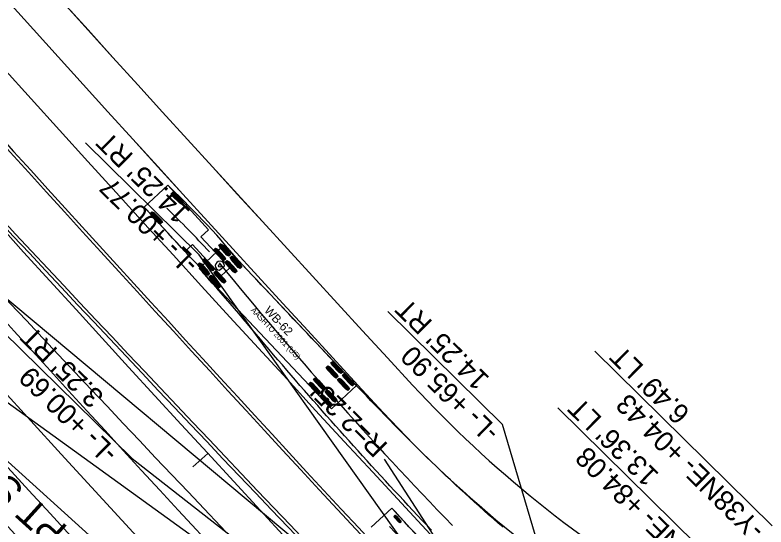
# Model space of a CAD drawing. Extents: x 1262642 to 1268358, y 767825 to 773481.
# Drawn here: x 1266608.5 to 1266795.4, y 772285.8 to 772413.2 of the extents above; entities that cross this region are included whole.
import ezdxf

# ---------------------------------------------------------------- set-up
doc = ezdxf.new("R2010")
doc.units = 0
for name, color, linetype in [('Prop Conc 1ft 6in Curb and Gutter', 7, 'Continuous'), ('Prop Dimension', 7, 'Continuous'), ('Prop Dimension Text', 7, 'Continuous'), ('Prop EOT', 7, 'Continuous'), ('Prop Horizontal Alignment', 7, 'Continuous'), ('Prop Horizontal Alignment Station Label', 7, 'Continuous'), ('Prop Horizontal Alignment Tick Small', 7, 'Continuous'), ('Prop Lane Lines', 7, 'Continuous'), ('Prop Paved Shoulder', 7, 'Continuous'), ('Prop Shade Light', 7, 'Continuous'), ('Scratch_Level_3', 7, 'Continuous')]:
    doc.layers.add(name, color=color, linetype=linetype)

msp = doc.modelspace()

# ---------------------------------------------------------------- linework, layer by layer
at = {"layer": 'Prop Conc 1ft 6in Curb and Gutter'}
for centre, radius, start, end in [((1275047.31, 780021.23), 11385.75, 220.946412, 223.103661), ((1274932.68, 780143.08), 11396.75, 221.786199, 223.669794)]:
    msp.add_arc(centre, radius, start, end, dxfattribs=at)
at = {"layer": 'Prop Dimension Text'}
for p, q in [((1266626.06, 772381.46), (1266654.37, 772353.57)), ((1266588.48, 772357.65), (1266689.12, 772273.54)), ((1266734.36, 772241.11), (1266654.37, 772353.57)), ((1266701.25, 772339.45), (1266729.84, 772311.28)), ((1266605.51, 772334.48), (1266637.67, 772302.8)), ((1266752.75, 772329.57), (1266796.9, 772286.07)), ((1266602.44, 772319.81), (1266679.28, 772264.3)), ((1266743.59, 772315.45), (1266784.1, 772275.52)), ((1266758.2, 772215.71), (1266729.84, 772311.28)), ((1266637.67, 772302.8), (1266726.39, 772233.53)), ((1266758.37, 772212.84), (1266700.47, 772302.68))]:
    msp.add_line(p, q, dxfattribs=at)
at = {"layer": 'Prop EOT'}
for centre, radius, start, end in [((1275047.31, 780021.23), 11361, 216.766365, 222.716029), ((1275047.31, 780021.23), 11439, 220.505091, 222.993587), ((1275047.31, 780021.23), 11385, 220.946412, 222.993587), ((1274932.68, 780143.08), 11397.5, 221.785983, 223.669794), ((1266920.52, 772517.83), 300, 222.716, 239.6427)]:
    msp.add_arc(centre, radius, start, end, dxfattribs=at)
at = {"layer": 'Prop Horizontal Alignment'}
msp.add_arc((1275047.31, 780021.23), 11400, 216.766365, 222.993587, dxfattribs=at)
at = {"layer": 'Prop Horizontal Alignment Station Label'}
msp.add_line((1266769.82, 772154.72), (1266566.88, 772338.06), dxfattribs=at)
at = {"layer": 'Prop Horizontal Alignment Tick Small'}
msp.add_line((1266656.47, 772304.11), (1266652.79, 772300.73), dxfattribs=at)
at = {"layer": 'Prop Lane Lines'}
for centre, radius, start, end in [((1275047.31, 780021.23), 11373, 216.364944, 223.132748), ((1275047.31, 780021.23), 11427, 216.367499, 223.547684), ((1275047.31, 780021.23), 11415, 220.946412, 223.104121), ((1274932.68, 780143.08), 11409.5, 221.786199, 223.669794)]:
    msp.add_arc(centre, radius, start, end, dxfattribs=at)
at = {"layer": 'Prop Paved Shoulder'}
for centre, radius, start, end in [((1275047.31, 780021.23), 11351, 216.766365, 222.716029), ((1275047.31, 780021.23), 11449, 220.505091, 223.202447), ((1266920.52, 772517.83), 290, 222.716, 239.652)]:
    msp.add_arc(centre, radius, start, end, dxfattribs=at)
at = {"layer": 'Prop Shade Light'}
for centre, radius, start, end in [((1275047.31, 780021.23), 11351, 216.765763, 222.716029), ((1275047.31, 780021.23), 11361, 216.765886, 222.716029), ((1275047.31, 780021.23), 11439, 220.505091, 222.993587), ((1275047.31, 780021.23), 11449, 220.505091, 223.202447), ((1266920.52, 772517.83), 290, 222.716, 239.652), ((1266920.52, 772517.83), 300, 222.716, 239.6427)]:
    msp.add_arc(centre, radius, start, end, dxfattribs=at)
at = {"layer": 'Scratch_Level_3'}
for p, q in [((1266646.53, 772370.85), (1266640.63, 772365.44)), ((1266656.67, 772359.8), (1266646.53, 772370.85)), ((1266647.42, 772368.74), (1266650.02, 772366.16)), ((1266647.58, 772368.9), (1266650.18, 772366.32)), ((1266647.74, 772369.06), (1266650.34, 772366.48)), ((1266640.63, 772365.44), (1266650.78, 772354.39)), ((1266640.63, 772365.44), (1266640.63, 772365.44)), ((1266642.39, 772364.08), (1266645, 772361.5)), ((1266642.55, 772364.24), (1266645.16, 772361.66)), ((1266642.23, 772363.91), (1266644.84, 772361.34)), ((1266654.78, 772358.06), (1266656.67, 772359.8)), ((1266661.94, 772350.27), (1266654.78, 772358.06)), ((1266650.78, 772354.39), (1266652.67, 772356.13)), ((1266652.67, 772356.13), (1266659.82, 772348.33)), ((1266660.5, 772355.93), (1266654.32, 772350.1)), ((1266658.05, 772354.84), (1266660.53, 772352.14)), ((1266658.22, 772355), (1266660.7, 772352.3)), ((1266658.39, 772355.15), (1266660.87, 772352.45)), ((1266659.26, 772355.96), (1266661.74, 772353.26)), ((1266659.43, 772356.11), (1266661.91, 772353.41)), ((1266659.6, 772356.27), (1266662.08, 772353.57)), ((1266693.45, 772321.02), (1266660.5, 772355.93)), ((1266662.08, 772352.89), (1266664.56, 772350.19)), ((1266662.25, 772353.04), (1266664.73, 772350.34)), ((1266662.42, 772353.2), (1266664.9, 772350.5)), ((1266654.05, 772351.17), (1266656.52, 772348.47)), ((1266654.21, 772351.32), (1266656.69, 772348.62)), ((1266654.38, 772351.48), (1266656.86, 772348.78)), ((1266655.26, 772352.28), (1266657.74, 772349.58)), ((1266655.43, 772352.44), (1266657.91, 772349.74)), ((1266655.6, 772352.59), (1266658.08, 772349.89)), ((1266660.87, 772351.77), (1266663.34, 772349.07)), ((1266661.03, 772351.93), (1266663.51, 772349.23)), ((1266661.2, 772352.08), (1266663.68, 772349.38)), ((1266654.32, 772350.1), (1266687.26, 772315.19)), ((1266654.32, 772350.1), (1266654.32, 772350.1)), ((1266658.08, 772349.21), (1266660.56, 772346.51)), ((1266658.25, 772349.37), (1266660.73, 772346.67)), ((1266658.42, 772349.52), (1266660.89, 772346.82)), ((1266659.42, 772349.69), (1266660.61, 772350.78)), ((1266659.82, 772348.33), (1266661.94, 772350.27)), ((1266656.86, 772348.1), (1266659.34, 772345.4)), ((1266657.03, 772348.25), (1266659.51, 772345.55)), ((1266657.2, 772348.41), (1266659.68, 772345.71)), ((1266687.17, 772326.67), (1266689.69, 772324)), ((1266687.34, 772326.83), (1266689.85, 772324.16)), ((1266687.5, 772326.98), (1266690.02, 772324.32)), ((1266685.97, 772325.54), (1266688.49, 772322.87)), ((1266686.14, 772325.69), (1266688.65, 772323.03)), ((1266686.3, 772325.85), (1266688.82, 772323.19)), ((1266690.03, 772323.64), (1266692.55, 772320.97)), ((1266690.2, 772323.8), (1266692.71, 772321.13)), ((1266690.36, 772323.95), (1266692.88, 772321.29)), ((1266681.65, 772321.47), (1266684.17, 772318.8)), ((1266681.82, 772321.62), (1266684.34, 772318.96)), ((1266681.99, 772321.78), (1266684.5, 772319.11)), ((1266682.85, 772322.6), (1266685.37, 772319.93)), ((1266683.02, 772322.76), (1266685.54, 772320.09)), ((1266683.19, 772322.91), (1266685.7, 772320.25)), ((1266688.83, 772322.51), (1266691.35, 772319.84)), ((1266689, 772322.66), (1266691.51, 772320)), ((1266689.16, 772322.82), (1266691.68, 772320.15)), ((1266685.71, 772319.57), (1266688.23, 772316.9)), ((1266685.88, 772319.72), (1266688.4, 772317.06)), ((1266686.05, 772319.88), (1266688.56, 772317.22)), ((1266687.26, 772315.19), (1266693.45, 772321.02)), ((1266684.51, 772318.43), (1266687.03, 772315.77)), ((1266684.68, 772318.59), (1266687.2, 772315.93)), ((1266684.85, 772318.75), (1266687.36, 772316.08)), ((1266702.23, 772290.51), (1266697.09, 772285.75)), ((1266715.14, 772276.56), (1266702.23, 772290.51)), ((1266702.83, 772288.51), (1266704.35, 772286.85)), ((1266702.94, 772288.6), (1266704.46, 772286.94)), ((1266703.04, 772288.7), (1266704.56, 772287.04))]:
    msp.add_line(p, q, dxfattribs=at)
for points in [[(1266729.93, 772285.73), (1266728.73, 772286.76), (1266727.54, 772287.8), (1266726.34, 772288.84), (1266725.15, 772289.9), (1266723.96, 772290.96), (1266722.77, 772292.03), (1266721.58, 772293.11), (1266720.4, 772294.19), (1266719.21, 772295.29), (1266718.02, 772296.4), (1266716.83, 772297.51), (1266715.65, 772298.63), (1266714.46, 772299.76), (1266713.28, 772300.89), (1266712.11, 772302.02), (1266710.93, 772303.17), (1266709.76, 772304.31), (1266708.6, 772305.46), (1266707.43, 772306.62), (1266706.27, 772307.78), (1266705.11, 772308.95), (1266703.95, 772310.12), (1266702.8, 772311.29), (1266701.65, 772312.47), (1266700.5, 772313.65), (1266699.36, 772314.83), (1266698.21, 772316.02), (1266697.07, 772317.21), (1266695.93, 772318.41), (1266694.8, 772319.6), (1266693.66, 772320.8), (1266692.52, 772322), (1266691.39, 772323.2), (1266690.26, 772324.4), (1266689.12, 772325.6), (1266687.99, 772326.81), (1266686.85, 772328.01), (1266685.72, 772329.21), (1266684.58, 772330.42), (1266683.44, 772331.62), (1266682.31, 772332.82), (1266681.17, 772334.03), (1266680.04, 772335.23), (1266678.9, 772336.44), (1266677.76, 772337.64), (1266676.63, 772338.84), (1266675.49, 772340.05), (1266674.35, 772341.25), (1266673.22, 772342.46), (1266672.08, 772343.66), (1266670.94, 772344.87), (1266669.8, 772346.08), (1266668.67, 772347.28), (1266667.53, 772348.49), (1266666.39, 772349.69), (1266665.25, 772350.9), (1266664.11, 772352.11), (1266663.02, 772353.36), (1266661.94, 772354.62), (1266660.87, 772355.89), (1266659.8, 772357.16), (1266658.72, 772358.43), (1266657.6, 772359.68), (1266656.44, 772360.89), (1266655.28, 772362.09), (1266654.11, 772363.29), (1266652.94, 772364.48), (1266651.76, 772365.67), (1266650.58, 772366.86), (1266649.4, 772368.04), (1266648.2, 772369.21), (1266647.01, 772370.38), (1266646.53, 772370.85)], [(1266712.1, 772284.98), (1266710.95, 772286.21), (1266709.8, 772287.43), (1266708.65, 772288.67), (1266707.51, 772289.9), (1266706.36, 772291.13), (1266705.22, 772292.36), (1266704.08, 772293.6), (1266702.94, 772294.83), (1266701.8, 772296.07), (1266700.67, 772297.31), (1266699.53, 772298.54), (1266698.4, 772299.79), (1266697.24, 772300.99), (1266696.11, 772302.23), (1266694.98, 772303.48), (1266693.86, 772304.72), (1266692.74, 772305.97), (1266691.62, 772307.22), (1266690.5, 772308.47), (1266689.38, 772309.72), (1266688.27, 772310.97), (1266687.15, 772312.23), (1266686.04, 772313.49), (1266684.93, 772314.74), (1266683.82, 772316), (1266682.72, 772317.26), (1266681.61, 772318.53), (1266680.51, 772319.79), (1266679.41, 772321.05), (1266678.31, 772322.32), (1266677.22, 772323.59), (1266676.12, 772324.86), (1266675.03, 772326.13), (1266673.94, 772327.4), (1266672.85, 772328.68), (1266671.76, 772329.95), (1266670.68, 772331.23), (1266669.59, 772332.51), (1266668.51, 772333.79), (1266667.43, 772335.07), (1266666.35, 772336.36), (1266665.28, 772337.64), (1266664.2, 772338.92), (1266663.11, 772340.19), (1266662.02, 772341.46), (1266660.92, 772342.73), (1266659.82, 772343.98), (1266658.71, 772345.24), (1266657.6, 772346.49), (1266656.48, 772347.73), (1266655.35, 772348.97), (1266654.49, 772350.47), (1266653.35, 772351.69), (1266652.2, 772352.9), (1266651.06, 772354.1), (1266649.94, 772355.3), (1266648.83, 772356.51), (1266647.72, 772357.72), (1266646.62, 772358.92), (1266645.51, 772360.13), (1266644.4, 772361.34), (1266643.29, 772362.55), (1266642.19, 772363.75), (1266641.08, 772364.96), (1266640.63, 772365.44)], [(1266728.12, 772262.74), (1266726.97, 772263.95), (1266725.83, 772265.16), (1266724.69, 772266.37), (1266723.54, 772267.58), (1266722.4, 772268.8), (1266721.26, 772270.01), (1266720.12, 772271.23), (1266718.99, 772272.44), (1266717.85, 772273.66), (1266716.71, 772274.87), (1266715.58, 772276.09), (1266714.45, 772277.31), (1266713.31, 772278.53), (1266712.18, 772279.75), (1266711.05, 772280.97), (1266709.92, 772282.2), (1266708.79, 772283.42), (1266707.66, 772284.64), (1266706.53, 772285.86), (1266705.4, 772287.08), (1266704.27, 772288.31), (1266703.14, 772289.53), (1266702.23, 772290.51)]]:
    msp.add_lwpolyline(points, dxfattribs=at)
for points in [[(1266647.38, 772368.7), (1266647.78, 772369.1), (1266648.27, 772368.86), (1266650.14, 772367.01), (1266650.38, 772366.52), (1266649.98, 772366.12), (1266649.5, 772366.36), (1266647.62, 772368.21)], [(1266642.19, 772363.87), (1266642.59, 772364.28), (1266643.08, 772364.04), (1266644.95, 772362.19), (1266645.2, 772361.7), (1266644.8, 772361.3), (1266644.31, 772361.53), (1266642.43, 772363.39)], [(1266658.01, 772354.8), (1266658.43, 772355.19), (1266658.9, 772354.93), (1266660.69, 772352.98), (1266660.91, 772352.49), (1266660.49, 772352.1), (1266660.01, 772352.36), (1266658.23, 772354.31)], [(1266659.22, 772355.92), (1266659.64, 772356.31), (1266660.12, 772356.04), (1266661.9, 772354.1), (1266662.12, 772353.61), (1266661.7, 772353.22), (1266661.23, 772353.48), (1266659.44, 772355.42)], [(1266662.04, 772352.85), (1266662.46, 772353.24), (1266662.93, 772352.97), (1266664.72, 772351.03), (1266664.94, 772350.54), (1266664.52, 772350.15), (1266664.04, 772350.41), (1266662.26, 772352.36)], [(1266654, 772351.13), (1266654.42, 772351.52), (1266654.9, 772351.26), (1266656.68, 772349.31), (1266656.9, 772348.82), (1266656.48, 772348.43), (1266656.01, 772348.69), (1266654.22, 772350.64)], [(1266655.22, 772352.25), (1266655.64, 772352.63), (1266656.11, 772352.37), (1266657.9, 772350.43), (1266658.12, 772349.93), (1266657.7, 772349.54), (1266657.22, 772349.81), (1266655.44, 772351.75)], [(1266660.82, 772351.73), (1266661.24, 772352.12), (1266661.72, 772351.86), (1266663.5, 772349.91), (1266663.72, 772349.42), (1266663.3, 772349.03), (1266662.83, 772349.29), (1266661.04, 772351.24)], [(1266658.04, 772349.18), (1266658.46, 772349.56), (1266658.93, 772349.3), (1266660.72, 772347.36), (1266660.94, 772346.86), (1266660.52, 772346.47), (1266660.04, 772346.74), (1266658.26, 772348.68)], [(1266656.82, 772348.06), (1266657.24, 772348.45), (1266657.72, 772348.19), (1266659.5, 772346.24), (1266659.72, 772345.75), (1266659.3, 772345.36), (1266658.83, 772345.62), (1266657.04, 772347.57)], [(1266687.13, 772326.63), (1266687.54, 772327.02), (1266688.02, 772326.77), (1266689.83, 772324.85), (1266690.06, 772324.36), (1266689.64, 772323.96), (1266689.17, 772324.22), (1266687.36, 772326.14)], [(1266685.93, 772325.5), (1266686.34, 772325.89), (1266686.82, 772325.64), (1266688.63, 772323.72), (1266688.86, 772323.22), (1266688.44, 772322.83), (1266687.97, 772323.09), (1266686.16, 772325.01)], [(1266682.81, 772322.56), (1266683.23, 772322.95), (1266683.71, 772322.7), (1266685.52, 772320.78), (1266685.75, 772320.28), (1266685.33, 772319.89), (1266684.85, 772320.15), (1266683.04, 772322.07)], [(1266689.99, 772323.6), (1266690.4, 772323.99), (1266690.88, 772323.74), (1266692.69, 772321.82), (1266692.92, 772321.33), (1266692.5, 772320.93), (1266692.03, 772321.19), (1266690.21, 772323.11)], [(1266681.61, 772321.43), (1266682.03, 772321.82), (1266682.51, 772321.56), (1266684.32, 772319.64), (1266684.55, 772319.15), (1266684.13, 772318.76), (1266683.65, 772319.01), (1266681.84, 772320.93)], [(1266688.79, 772322.47), (1266689.2, 772322.86), (1266689.68, 772322.61), (1266691.49, 772320.69), (1266691.72, 772320.19), (1266691.3, 772319.8), (1266690.83, 772320.06), (1266689.01, 772321.98)], [(1266685.67, 772319.53), (1266686.09, 772319.92), (1266686.57, 772319.67), (1266688.38, 772317.75), (1266688.6, 772317.25), (1266688.19, 772316.86), (1266687.71, 772317.12), (1266685.9, 772319.04)], [(1266684.47, 772318.4), (1266684.89, 772318.79), (1266685.37, 772318.53), (1266687.18, 772316.61), (1266687.4, 772316.12), (1266686.99, 772315.73), (1266686.51, 772315.98), (1266684.7, 772317.9)], [(1266702.81, 772288.48), (1266703.07, 772288.72), (1266703.36, 772288.56), (1266704.45, 772287.36), (1266704.59, 772287.06), (1266704.33, 772286.82), (1266704.04, 772286.98), (1266702.94, 772288.18)]]:
    msp.add_lwpolyline(points, close=True, dxfattribs=at)
msp.add_circle((1266659.47, 772350.83), 0.34, dxfattribs=at)
for centre, radius, start, end in [((1266359.91, 772075.79), 407.14, 43.1576, 45.302), ((1266659.47, 772350.83), 1.14, 357.5437, 267.5437), ((1267463.63, 773007.3), 1037.77, 219.19194, 224.01928), ((1268163.05, 773623.07), 1980.78, 222.45873, 224.38845)]:
    msp.add_arc(centre, radius, start, end, dxfattribs=at)

# ---------------------------------------------------------------- texts
at = {"layer": 'Prop Dimension'}
msp.add_text("R=2.25'", height=5, rotation=135.4239, dxfattribs=at).set_placement((1266701.51, 772306.27))
at = {"layer": 'Prop Dimension Text'}
for s, p in [("14.25' RT", (1266652.38, 772364.37)), ('-L- +00.77', (1266654.52, 772351.74)), ("14.25' RT", (1266726.8, 772322.89)), ("3.25' RT", (1266630.91, 772318.55)), ('-L- +65.90', (1266729.38, 772309.82)), ("6.49' LT", (1266776.72, 772314.45)), ('-L- +00.69', (1266634.39, 772304.59)), ('-Y38NE- +04.43', (1266795.38, 772285.54)), ("13.36' LT", (1266768.98, 772298.95)), ('-Y38NE- +84.08', (1266785.28, 772272.36))]:
    msp.add_text(s, height=5, rotation=135.4239, dxfattribs=at).set_placement(p)
at = {"layer": 'Prop Horizontal Alignment Station Label'}
msp.add_text('PT Sta.  18+18.75', height=7, rotation=137.9038, dxfattribs=at).set_placement((1266621.93, 772285.63))
at = {"layer": 'Scratch_Level_3'}
for s, height, p in [('AASHTO 2001 (US)', 1.4167, (1266667.07, 772339.67)), ('WB-62', 2.125, (1266670.36, 772339.54)), ('(c) 2016 Transoft Solutions, Inc. All rights reserved.', 0.085, (1266672.66, 772336.79))]:
    msp.add_text(s, height=height, rotation=313.3379, dxfattribs=at).set_placement(p)

doc.saveas('drawing.dxf')
